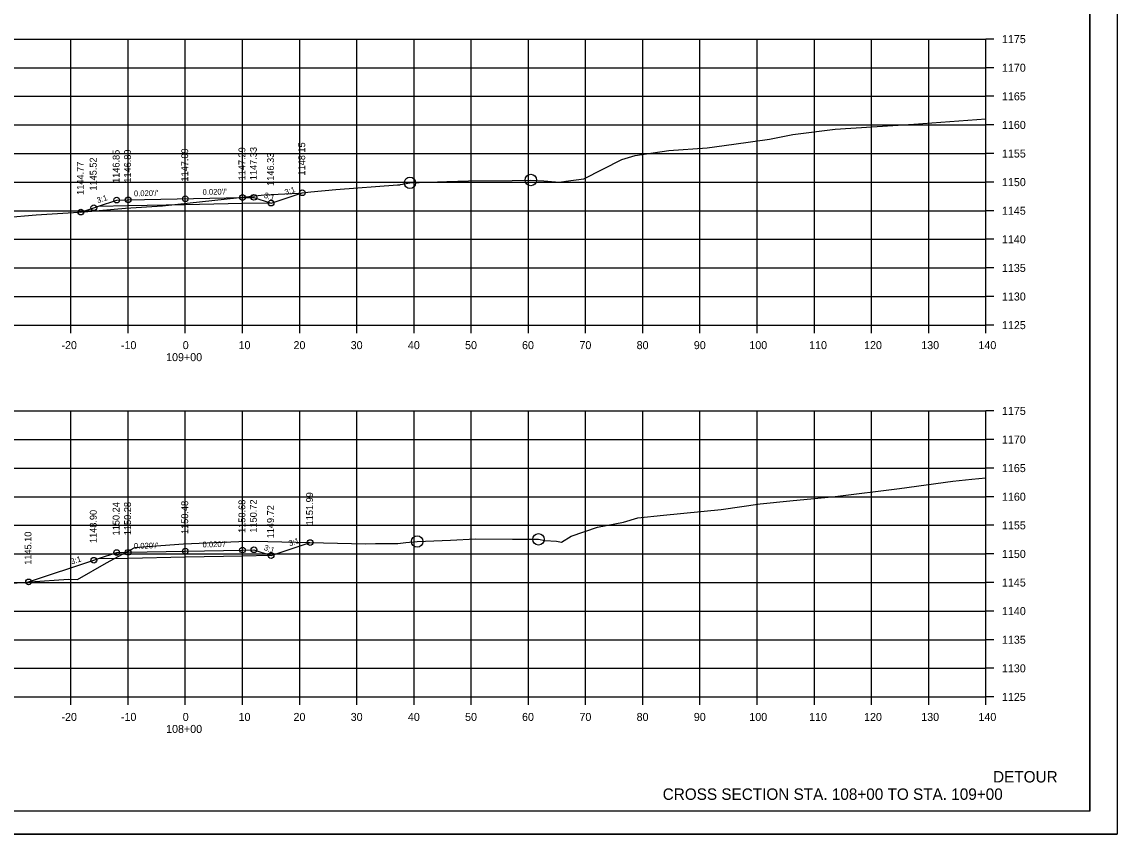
# Model space of a CAD drawing. Extents: x 1368971 to 1374497, y 378717 to 381839.
# Drawn here: x 1371234.1 to 1371425.6, y 381199.4 to 381341.4 of the extents above; entities that cross this region are included whole.
import ezdxf

# ---------------------------------------------------------------- set-up
doc = ezdxf.new("R2010")
doc.units = 0
for name, color, linetype in [('R_Alt Surface', 7, 'Continuous'), ('R_Axis', 7, 'Continuous'), ('R_Axis Annot', 7, 'Continuous'), ('R_Draft', 7, 'Continuous'), ('R_Exist Surface', 7, 'Continuous'), ('R_Fin Surface', 7, 'Continuous'), ('R_Grid', 7, 'Continuous'), ('R_No Plot', 7, 'Continuous'), ('R_Xsect Elev', 7, 'Continuous'), ('R_Xsect Slope', 7, 'Continuous')]:
    doc.layers.add(name, color=color, linetype=linetype)

msp = doc.modelspace()

# ---------------------------------------------------------------- linework, layer by layer
at = {"layer": 'R_Alt Surface'}
for points in [[(1371247.45, 381309.2), (1371252.64, 381309.31), (1371262.64, 381309.51), (1371272.64, 381309.71), (1371277.47, 381309.8)], [(1371247.45, 381247.58), (1371252.64, 381247.69), (1371262.64, 381247.89), (1371272.64, 381248.09), (1371277.47, 381248.18)]]:
    msp.add_lwpolyline(points, dxfattribs=at)
at = {"layer": 'R_Axis'}
for p, q in [((1371402.64, 381288.41), (1371402.64, 381338.41)), ((1371404.04, 381338.41), (1371402.64, 381338.41)), ((1371404.04, 381333.41), (1371402.64, 381333.41)), ((1371404.04, 381328.41), (1371402.64, 381328.41)), ((1371404.04, 381323.41), (1371402.64, 381323.41)), ((1371404.04, 381318.41), (1371402.64, 381318.41)), ((1371404.04, 381313.41), (1371402.64, 381313.41)), ((1371404.04, 381308.41), (1371402.64, 381308.41)), ((1371404.04, 381303.41), (1371402.64, 381303.41)), ((1371404.04, 381298.41), (1371402.64, 381298.41)), ((1371404.04, 381293.41), (1371402.64, 381293.41)), ((1371122.64, 381288.41), (1371402.64, 381288.41)), ((1371242.64, 381287.01), (1371242.64, 381288.41)), ((1371252.64, 381287.01), (1371252.64, 381288.41)), ((1371262.64, 381287.01), (1371262.64, 381288.41)), ((1371272.64, 381287.01), (1371272.64, 381288.41)), ((1371282.64, 381287.01), (1371282.64, 381288.41)), ((1371292.64, 381287.01), (1371292.64, 381288.41)), ((1371302.64, 381287.01), (1371302.64, 381288.41)), ((1371312.64, 381287.01), (1371312.64, 381288.41)), ((1371322.64, 381287.01), (1371322.64, 381288.41)), ((1371332.64, 381287.01), (1371332.64, 381288.41)), ((1371342.64, 381287.01), (1371342.64, 381288.41)), ((1371352.64, 381287.01), (1371352.64, 381288.41)), ((1371362.64, 381287.01), (1371362.64, 381288.41)), ((1371372.64, 381287.01), (1371372.64, 381288.41)), ((1371382.64, 381287.01), (1371382.64, 381288.41)), ((1371392.64, 381287.01), (1371392.64, 381288.41)), ((1371402.64, 381287.01), (1371402.64, 381288.41)), ((1371404.04, 381288.41), (1371402.64, 381288.41)), ((1371402.64, 381223.41), (1371402.64, 381273.41)), ((1371404.04, 381273.41), (1371402.64, 381273.41)), ((1371404.04, 381268.41), (1371402.64, 381268.41)), ((1371404.04, 381263.41), (1371402.64, 381263.41)), ((1371404.04, 381258.41), (1371402.64, 381258.41)), ((1371404.04, 381253.41), (1371402.64, 381253.41)), ((1371404.04, 381248.41), (1371402.64, 381248.41)), ((1371404.04, 381243.41), (1371402.64, 381243.41)), ((1371404.04, 381238.41), (1371402.64, 381238.41)), ((1371404.04, 381233.41), (1371402.64, 381233.41)), ((1371404.04, 381228.41), (1371402.64, 381228.41)), ((1371122.64, 381223.41), (1371402.64, 381223.41)), ((1371242.64, 381222.01), (1371242.64, 381223.41)), ((1371252.64, 381222.01), (1371252.64, 381223.41)), ((1371262.64, 381222.01), (1371262.64, 381223.41)), ((1371272.64, 381222.01), (1371272.64, 381223.41)), ((1371282.64, 381222.01), (1371282.64, 381223.41)), ((1371292.64, 381222.01), (1371292.64, 381223.41)), ((1371302.64, 381222.01), (1371302.64, 381223.41)), ((1371312.64, 381222.01), (1371312.64, 381223.41)), ((1371322.64, 381222.01), (1371322.64, 381223.41)), ((1371332.64, 381222.01), (1371332.64, 381223.41)), ((1371342.64, 381222.01), (1371342.64, 381223.41)), ((1371352.64, 381222.01), (1371352.64, 381223.41)), ((1371362.64, 381222.01), (1371362.64, 381223.41)), ((1371372.64, 381222.01), (1371372.64, 381223.41)), ((1371382.64, 381222.01), (1371382.64, 381223.41)), ((1371392.64, 381222.01), (1371392.64, 381223.41)), ((1371402.64, 381222.01), (1371402.64, 381223.41)), ((1371404.04, 381223.41), (1371402.64, 381223.41))]:
    msp.add_line(p, q, dxfattribs=at)
at = {"layer": 'R_Exist Surface'}
for points in [[(1371231.16, 381307.24), (1371236.57, 381307.71), (1371244.94, 381308.21), (1371252.2, 381308.85), (1371258.66, 381309.27), (1371276.42, 381311.17), (1371282.5, 381311.49), (1371284.61, 381311.74), (1371288.96, 381312.14), (1371299.72, 381312.91), (1371300.15, 381312.96), (1371300.28, 381312.99), (1371301.92, 381313.27), (1371308.36, 381313.5), (1371312.17, 381313.64), (1371319.77, 381313.72), (1371323.06, 381313.78), (1371325.33, 381313.62), (1371328.06, 381313.43), (1371329.16, 381313.55), (1371332.31, 381313.96), (1371338.97, 381317.37), (1371341.29, 381318.08), (1371347.17, 381318.91), (1371353.89, 381319.41), (1371358.56, 381320.07), (1371364.79, 381320.93), (1371368.86, 381321.73), (1371376.29, 381322.64), (1371390.01, 381323.55), (1371402.64, 381324.48)], [(1371231.05, 381243.19), (1371235.54, 381243.53), (1371242.23, 381244), (1371243.79, 381243.96), (1371248.87, 381246.86), (1371253.79, 381249.52), (1371255.22, 381249.67), (1371262.35, 381250.2), (1371272.01, 381250.6), (1371274.91, 381250.65), (1371277.08, 381250.58), (1371294.17, 381250.17), (1371295.9, 381250.23), (1371299.78, 381250.22), (1371301.19, 381250.4), (1371303.2, 381250.58), (1371309.02, 381250.81), (1371313.41, 381251.02), (1371319.86, 381250.99), (1371324.41, 381250.96), (1371325.48, 381250.77), (1371327.56, 381250.63), (1371328.45, 381250.47), (1371330.12, 381251.49), (1371334.71, 381253.08), (1371339.25, 381253.97), (1371341.78, 381254.72), (1371346.25, 381255.16), (1371356.32, 381256.19), (1371363.17, 381257.16), (1371368.36, 381257.71), (1371376.25, 381258.44), (1371387.52, 381259.83), (1371396.86, 381261.13), (1371400.18, 381261.45), (1371402.64, 381261.74)]]:
    msp.add_lwpolyline(points, dxfattribs=at)
at = {"layer": 'R_Fin Surface'}
for points in [[(1371244.38, 381308.18), (1371246.64, 381308.93), (1371247.45, 381309.2), (1371250.64, 381310.27), (1371252.64, 381310.31), (1371272.64, 381310.71), (1371274.64, 381310.75), (1371277.47, 381309.8), (1371277.64, 381309.75), (1371283.1, 381311.56)], [(1371235.23, 381243.51), (1371246.64, 381247.31), (1371247.45, 381247.58), (1371250.64, 381248.65), (1371252.64, 381248.69), (1371272.64, 381249.09), (1371274.64, 381249.13), (1371277.47, 381248.18), (1371277.64, 381248.13), (1371284.47, 381250.4)]]:
    msp.add_lwpolyline(points, dxfattribs=at)
at = {"layer": 'R_Grid'}
for p, q in [((1371122.64, 381338.41), (1371402.64, 381338.41)), ((1371242.64, 381288.41), (1371242.64, 381338.41)), ((1371252.64, 381288.41), (1371252.64, 381338.41)), ((1371262.64, 381288.41), (1371262.64, 381338.41)), ((1371272.64, 381288.41), (1371272.64, 381338.41)), ((1371282.64, 381288.41), (1371282.64, 381338.41)), ((1371292.64, 381288.41), (1371292.64, 381338.41)), ((1371302.64, 381288.41), (1371302.64, 381338.41)), ((1371312.64, 381288.41), (1371312.64, 381338.41)), ((1371322.64, 381288.41), (1371322.64, 381338.41)), ((1371332.64, 381288.41), (1371332.64, 381338.41)), ((1371342.64, 381288.41), (1371342.64, 381338.41)), ((1371352.64, 381288.41), (1371352.64, 381338.41)), ((1371362.64, 381288.41), (1371362.64, 381338.41)), ((1371372.64, 381288.41), (1371372.64, 381338.41)), ((1371382.64, 381288.41), (1371382.64, 381338.41)), ((1371392.64, 381288.41), (1371392.64, 381338.41)), ((1371402.64, 381288.41), (1371402.64, 381338.41)), ((1371122.64, 381333.41), (1371402.64, 381333.41)), ((1371122.64, 381328.41), (1371402.64, 381328.41)), ((1371122.64, 381323.41), (1371402.64, 381323.41)), ((1371122.64, 381318.41), (1371402.64, 381318.41)), ((1371122.64, 381313.41), (1371402.64, 381313.41)), ((1371122.64, 381308.41), (1371402.64, 381308.41)), ((1371122.64, 381303.41), (1371402.64, 381303.41)), ((1371122.64, 381298.41), (1371402.64, 381298.41)), ((1371122.64, 381293.41), (1371402.64, 381293.41)), ((1371122.64, 381288.41), (1371402.64, 381288.41)), ((1371122.64, 381273.41), (1371402.64, 381273.41)), ((1371242.64, 381223.41), (1371242.64, 381273.41)), ((1371252.64, 381223.41), (1371252.64, 381273.41)), ((1371262.64, 381223.41), (1371262.64, 381273.41)), ((1371272.64, 381223.41), (1371272.64, 381273.41)), ((1371282.64, 381223.41), (1371282.64, 381273.41)), ((1371292.64, 381223.41), (1371292.64, 381273.41)), ((1371302.64, 381223.41), (1371302.64, 381273.41)), ((1371312.64, 381223.41), (1371312.64, 381273.41)), ((1371322.64, 381223.41), (1371322.64, 381273.41)), ((1371332.64, 381223.41), (1371332.64, 381273.41)), ((1371342.64, 381223.41), (1371342.64, 381273.41)), ((1371352.64, 381223.41), (1371352.64, 381273.41)), ((1371362.64, 381223.41), (1371362.64, 381273.41)), ((1371372.64, 381223.41), (1371372.64, 381273.41)), ((1371382.64, 381223.41), (1371382.64, 381273.41)), ((1371392.64, 381223.41), (1371392.64, 381273.41)), ((1371402.64, 381223.41), (1371402.64, 381273.41)), ((1371122.64, 381268.41), (1371402.64, 381268.41)), ((1371122.64, 381263.41), (1371402.64, 381263.41)), ((1371122.64, 381258.41), (1371402.64, 381258.41)), ((1371122.64, 381253.41), (1371402.64, 381253.41)), ((1371122.64, 381248.41), (1371402.64, 381248.41)), ((1371122.64, 381243.41), (1371402.64, 381243.41)), ((1371122.64, 381238.41), (1371402.64, 381238.41)), ((1371122.64, 381233.41), (1371402.64, 381233.41)), ((1371122.64, 381228.41), (1371402.64, 381228.41)), ((1371122.64, 381223.41), (1371402.64, 381223.41))]:
    msp.add_line(p, q, dxfattribs=at)
at = {"layer": 'R_No Plot'}
for p, q in [((1371420.82, 381203.41), (1371420.82, 381408.87)), ((1371420.82, 381203.41), (1371104.64, 381203.41)), ((1371092.24, 381199.43), (1371425.58, 381199.43))]:
    msp.add_line(p, q, dxfattribs=at)
for points in [[(1371092.24, 381412.77), (1371425.58, 381412.77), (1371425.58, 381199.43), (1371092.24, 381199.43)], [(1371338.56, 381408.87), (1371338.56, 381398.99), (1371374.3, 381398.99), (1371374.3, 381396.07), (1371397.49, 381396.07), (1371397.49, 381372.86), (1371420.82, 381372.86), (1371420.82, 381203.41), (1371104.64, 381203.41), (1371104.64, 381408.87)]]:
    msp.add_lwpolyline(points, close=True, dxfattribs=at)
for centre, radius in [((1371301.92, 381313.27), 1), ((1371323.06, 381313.78), 1), ((1371283.1, 381311.56), 0.5), ((1371250.64, 381310.27), 0.5), ((1371252.64, 381310.31), 0.5), ((1371262.64, 381310.51), 0.5), ((1371272.64, 381310.71), 0.5), ((1371274.64, 381310.75), 0.5), ((1371277.64, 381309.75), 0.5), ((1371244.38, 381308.18), 0.5), ((1371246.64, 381308.93), 0.5), ((1371284.47, 381250.4), 0.5), ((1371303.2, 381250.58), 1), ((1371324.41, 381250.96), 1), ((1371250.64, 381248.65), 0.5), ((1371252.64, 381248.69), 0.5), ((1371262.64, 381248.89), 0.5), ((1371272.64, 381249.09), 0.5), ((1371274.64, 381249.13), 0.5), ((1371277.64, 381248.13), 0.5), ((1371246.64, 381247.31), 0.5), ((1371235.23, 381243.51), 0.5)]:
    msp.add_circle(centre, radius, dxfattribs=at)

# ---------------------------------------------------------------- texts
at = {"layer": 'R_Axis Annot'}
for s, p in [('1175', (1371405.44, 381337.71)), ('1170', (1371405.44, 381332.71)), ('1165', (1371405.44, 381327.71)), ('1160', (1371405.44, 381322.71)), ('1155', (1371405.44, 381317.71)), ('1150', (1371405.44, 381312.71)), ('1145', (1371405.44, 381307.71)), ('1140', (1371405.44, 381302.71)), ('1135', (1371405.44, 381297.71)), ('1130', (1371405.44, 381292.71)), ('1125', (1371405.44, 381287.71)), ('-20', (1371240.98, 381284.21)), ('-10', (1371251.38, 381284.21)), ('0', (1371262.19, 381284.21)), ('10', (1371271.95, 381284.21)), ('20', (1371281.56, 381284.21)), ('30', (1371291.56, 381284.21)), ('40', (1371301.56, 381284.21)), ('50', (1371311.56, 381284.21)), ('60', (1371321.52, 381284.21)), ('70', (1371331.56, 381284.21)), ('80', (1371341.56, 381284.21)), ('90', (1371351.56, 381284.21)), ('100', (1371361.27, 381284.21)), ('110', (1371371.72, 381284.21)), ('120', (1371381.33, 381284.21)), ('130', (1371391.33, 381284.21)), ('140', (1371401.33, 381284.21)), ('109+00', (1371259.28, 381282.11)), ('1175', (1371405.44, 381272.71)), ('1170', (1371405.44, 381267.71)), ('1165', (1371405.44, 381262.71)), ('1160', (1371405.44, 381257.71)), ('1155', (1371405.44, 381252.71)), ('1150', (1371405.44, 381247.71)), ('1145', (1371405.44, 381242.71)), ('1140', (1371405.44, 381237.71)), ('1135', (1371405.44, 381232.71)), ('1130', (1371405.44, 381227.71)), ('1125', (1371405.44, 381222.71)), ('-20', (1371240.98, 381219.21)), ('-10', (1371251.38, 381219.21)), ('0', (1371262.19, 381219.21)), ('10', (1371271.95, 381219.21)), ('20', (1371281.56, 381219.21)), ('30', (1371291.56, 381219.21)), ('40', (1371301.56, 381219.21)), ('50', (1371311.56, 381219.21)), ('60', (1371321.52, 381219.21)), ('70', (1371331.56, 381219.21)), ('80', (1371341.56, 381219.21)), ('90', (1371351.56, 381219.21)), ('100', (1371361.27, 381219.21)), ('110', (1371371.72, 381219.21)), ('120', (1371381.33, 381219.21)), ('130', (1371391.33, 381219.21)), ('140', (1371401.33, 381219.21)), ('108+00', (1371259.28, 381217.11))]:
    msp.add_text(s, height=1.4, dxfattribs=at).set_placement(p)
at = {"layer": 'R_Draft'}
for s, p in [('DETOUR', (1371403.89, 381208.45)), ('CROSS SECTION STA. 108+00 TO STA. 109+00', (1371346.12, 381205.41))]:
    msp.add_text(s, height=2, dxfattribs=at).set_placement(p)
at = {"layer": 'R_Xsect Elev'}
for s, p in [('1147.09', (1371263.14, 381313.51)), ('1147.29', (1371273.14, 381313.71)), ('1147.33', (1371275.14, 381313.75)), ('1148.15', (1371283.6, 381314.56)), ('1145.52', (1371247.14, 381311.93)), ('1146.85', (1371251.14, 381313.27)), ('1146.89', (1371253.14, 381313.31)), ('1146.33', (1371278.14, 381312.75)), ('1144.77', (1371244.88, 381311.18)), ('1151.99', (1371284.97, 381253.4)), ('1148.90', (1371247.14, 381250.31)), ('1150.24', (1371251.14, 381251.65)), ('1150.28', (1371253.14, 381251.69)), ('1150.48', (1371263.14, 381251.89)), ('1150.68', (1371273.14, 381252.09)), ('1150.72', (1371275.14, 381252.13)), ('1149.72', (1371278.14, 381251.13)), ('1145.10', (1371235.73, 381246.51))]:
    msp.add_text(s, height=1.2, rotation=90, dxfattribs=at).set_placement(p)
at = {"layer": 'R_Xsect Slope'}
for s, rotation, p in [("0.020'/'", 1.1458, (1371253.66, 381310.93)), ("0.020'/'", 1.1458, (1371265.66, 381311.17)), ('3:1', 341.5668, (1371276.3, 381310.72)), ('3:1', 18.4349, (1371280.21, 381311.13)), ('3:1', 18.4338, (1371247.35, 381309.7)), ("0.020'/'", 1.1458, (1371253.66, 381249.31)), ("0.020'/'", 1.1458, (1371265.66, 381249.55)), ('3:1', 18.4349, (1371280.9, 381249.74)), ('3:1', 341.5668, (1371276.3, 381249.1)), ('3:1', 18.4345, (1371242.78, 381246.55))]:
    msp.add_text(s, height=1, rotation=rotation, dxfattribs=at).set_placement(p)

doc.saveas('drawing.dxf')
